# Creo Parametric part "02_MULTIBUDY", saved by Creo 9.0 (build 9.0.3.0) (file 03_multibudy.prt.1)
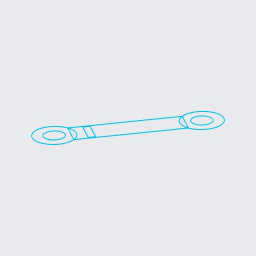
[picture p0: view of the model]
Materials in the file: S235JRG2

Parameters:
  BENENNUNG = "XXX"
  DATUM = "XX.XX.XX"
  ERSTELLER = "ARINDA"
  TEILETYP = "Fertigungsteil"
  PTC_MASTER_MATERIAL = "S235JRG2"
  SELECT_EN_NAME = "S235JRG2"
  SELECT_DIN_NAME = "RSt37-2"
  SELECT_DIN_NUMBER = "1.0038"
  SELECT_ASTM_NAME = "A 283 M Grade 2"
  MATERIAL_GROUP = "ME_ST_Baustahl"
  STANDARD_EN_DELIVERYSPEC = "DIN EN 10025"
  STANDARD_DIN_DELIVERYSPEC = "DIN 17100"

Other parameters: MASSE

Created from: ARINDA-STARTTEIL.PRT

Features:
  1. coordinate system "CS0"
  2. datum plane "DTM1", "T_RECHTS_Y-Z"
  3. datum plane "DTM2", "T_OBEN_X-Z"
  4. datum plane "DTM3", "T_VORNE_X-Y"
  5. datum axis "T_X-ACHSE"
  6. datum axis "A_1"
  7. datum axis "A_2"
  8. datum plane "DTM1", "P_SPIEGEL_1"
  9. datum plane "DTM2", "P_SPIEGEL_2"
  10. sketch "Skizze 1"

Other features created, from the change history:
  extrusion "Profil 1"
  extrusion "Profil 2"
  extrusion "Profil 3"
  pattern "Muster 1"
  extrusion "Profil 3 [3]"
  extrusion "Profil 3 [4]"
  extrusion "Profil 3 [2]"
  feature "Körper Trennen 1"

Other named items: T_BASIC, T_Y-ACHSE, T_Z-ACHSE

Layers: 00_STD-ACHSEN, 00_STD-EBENEN, 00_STD-KOORDSYS, 01_EBENEN, 01_KURVEN, KURVENELEMENTE, VOLUMENGEOMETRIE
